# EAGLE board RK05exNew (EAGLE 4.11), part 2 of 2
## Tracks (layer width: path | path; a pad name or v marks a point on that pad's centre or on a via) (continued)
N$3 (continued)
  Top 0.508: E11.13 53.98,139.06 55.24,139.06 E11.12 56.52,140.34 57.78,141.6 80.01,141.6 80.01,137.16 81.28,135.89 81.28,133.35 E10.3
  Bottom 0.508: E10.3 81.92,132.72 83.19,133.99 84.45,133.99 85.72,132.72 E10.5
N$4  (via drill 0.61)
  Top 0.508: v78.74,128.91 78.74,130.81 E10.2 | v85.72,128.91 88.27,131.44 E10.6
  Bottom 0.508: v78.74,128.91 v85.72,128.91
N$5  (via drill 0.61)
  Top 0.508: R10.1 215.9,144.15 215.9,140.97 E2.10 215.9,138.43 213.36,135.89 213.36,133.35 E2.4 213.36,130.81 v213.36,128.91 | v134.62,126.36 134.62,102.87 E5.10
  Bottom 0.508: v134.62,126.36 137.16,128.91 v213.36,128.91
N$6
  Top 0.508: E7.4 78.74,95.25 78.74,100.33 E7.11
N$7
  Top 0.508: E7.5 81.92,93.34 83.19,92.08 85.09,92.08 85.09,99.06 86.36,100.33 E7.8
N$8
  Top 0.508: E11.3 56.52,132.72 62.87,139.06 E11.9
N$9  (via drill 0.61)
  Top 0.508: v83.82,98.42 83.82,100.33 E7.9 | v173.99,99.06 173.99,102.87 176.53,105.41 v176.53,107.31 | v189.23,113.03 190.5,114.3 190.5,127 194.31,130.81 194.31,137.16 195.58,138.43 E4.8
  Bottom 0.508: v83.82,98.42 139.06,98.42 139.7,99.06 v173.99,99.06 | v176.53,107.31 182.25,113.03 v189.23,113.03
N$10
  Top 0.508: R20.1 238.76,38.73 238.76,40.01 C36.1 | E13.3 243.84,11.43 242.57,12.7 242.57,39.37 Q1.E
  Bottom 0.508: R20.1 239.4,38.1 240.66,39.37 241.3,39.37 Q1.E
N$11
  Top 0.508: E8.14 132.08,140.97 132.08,141.6 139.7,149.22 171.45,149.22 171.45,138.43 172.72,137.16 172.72,135.25 C63.2
N$12
  Top 0.508: E8.6 139.7,133.35 143.51,137.16 143.51,140.97 139.7,144.78 137.79,144.78 C62.2
N$13
  Top 0.508: R9.E 161.29,147.32 158.75,144.78 R9.S
  Bottom 0.508: 153.67,142.88 155.57,144.78 156.21,144.78 R9.S | 153.67,142.88 148.59,137.79 131.44,137.79 130.18,139.06 E8.15 | 153.67,142.88 171.45,142.88 172.09,142.24 C63.1
N$14  (via drill 0.61)
  Top 0.508: v143.51,135.25 143.51,134.62 142.24,133.35 E8.7 | v146.05,135.25 146.05,142.88 144.78,144.15 C62.1 144.78,145.41 144.78,146.69 R8.1
  Bottom 0.508: v143.51,135.25 v146.05,135.25
N$15
  Top 0.508: E7.3 76.83,93.34 78.11,92.08 80.01,92.08 80.01,135.89 78.74,137.16 78.74,138.43 E10.13
N$16
  Top 0.508: R21.1 243.84,36.2 243.84,37.47 Q1.B1
N$17
  Top 0.508: Q1.B2 243.84,41.27 243.84,42.55 R22.2
N$18  (via drill 0.61)
  Top 0.508: R22.1 233.68,43.81 233.68,45.09 R23.2 | 187.96,19.05 185.42,21.59 185.42,22.23 C37.2 | 187.96,19.05 E12.13 187.96,19.05 | v191.77,46.99 190.5,45.72 190.5,30.48 187.96,27.94 187.96,19.05
  Bottom 0.508: v191.77,46.99 194.31,49.53 198.75,49.53 202.56,45.72 233.04,45.72 R23.2
N$19  (via drill 0.61)
  Top 0.508: C37.1 193.04,22.23 193.04,21.59 190.5,19.05 E12.12 190.5,16.51 v190.5,14.61 | v89.53,40.01 92.71,36.83 92.71,26.67 100.33,19.05 v100.33,13.34 | v224.79,14.61 224.79,15.24 226.06,16.51 E14.10
  Bottom 0.508: v89.53,40.01 80.01,40.01 76.2,43.81 47.62,43.81 31.11,60.33 E22.1 | 190.5,13.34 210.19,13.34 211.46,12.06 | v100.33,13.34 190.5,13.34 | 211.46,12.06 212.72,10.79 E14.2 | v224.79,14.61 222.25,12.06 211.46,12.06 | 190.5,13.34 v190.5,14.61
N$20  (via drill 0.61)
  Top 0.508: v91.44,8.26 91.44,4.45 94.61,1.27 108.58,1.27 108.58,9.53 E17.6
  Bottom 0.508: v91.44,8.26 94.61,8.26 95.89,9.53 E17.1
N$21  (via drill 0.61)
  Top 0.508: v101.6,50.8 102.87,49.53 102.87,39.37 105.41,36.83 105.41,30.48 102.87,27.94 102.87,15.24 101.6,13.97 101.6,11.43 E17.3
  Bottom 0.508: E17.3 102.23,9.53 103.5,9.53 E17.4 | v101.6,50.8 90.81,50.8 90.17,50.16 84.45,50.16 80.01,54.61 59.69,54.61 57.15,57.15 52.07,57.15 48.9,60.33 E21.1
N$22  (via drill 0.61)
  Top 0.508: E14.15 213.36,19.05 213.36,22.23 C35.1 214,22.86 v216.53,25.4
  Bottom 0.508: v216.53,25.4 220.34,25.4 R25.1
N$23
  Top 0.508: E14.14 216.53,18.41 220.34,22.23 220.34,22.86 C35.2
N$24
  Top 0.508: R28.1 226.06,5.71 226.06,8.89 E14.7 226.06,11.43 227.33,12.7 227.33,19.68 230.5,22.86 C25.1
N$25
  Top 0.508: E14.6 223.52,11.43 222.25,12.7 222.25,20.95 223.52,22.23 C25.2
N$26  (via drill 0.61)
  Top 0.508: v25.4,13.34 25.4,12.7 23.5,10.79 E20.4 | v49.53,14.61 50.8,15.88 50.8,16.51 E19.13
  Bottom 0.508: v25.4,13.34 26.67,14.61 v49.53,14.61
N$27
  Top 0.508: E20.5 25.4,8.89 25.4,6.35 30.48,1.27 52.07,1.27 52.07,15.24 53.34,16.51 E19.12
N$28
  Top 0.508: E19.5 53.98,9.53 56.52,6.99 83.82,6.99 83.82,8.89 E16.6
N$29
  Top 0.508: E3.15 167.64,64.77 168.91,66.04 168.91,71.75 170.18,73.03 170.18,128.27 167.64,130.81 E6.6
N$30
  Bottom 0.508: RUN.2 29.21,84.45 33.02,88.27 41.91,88.27 RTZ.1
N$31  (via drill 0.61)
  Top 0.508: v160.02,144.15 160.02,140.97 E6.12 | v180.97,144.15 184.15,140.97 v184.15,72.39 | v173.99,70.48 170.18,66.67 170.18,64.77 E3.14
  Bottom 0.508: v180.97,144.15 v160.02,144.15 | v184.15,72.39 182.25,70.48 v173.99,70.48
N$32  (via drill 0.61)
  Top 0.508: v160.66,135.25 158.75,133.35 158.75,99.69 160.02,98.42 160.02,72.39 v165.1,67.31
  Bottom 0.508: v160.66,135.25 164.47,139.06 E6.10 | v165.1,67.31 167,65.41 170.81,65.41 172.09,64.14 E3.13
N$33
  Top 0.508: E6.8 170.18,138.43 171.45,137.16 171.45,122.56 173.99,120.02 173.99,104.14 172.72,102.87 172.72,73.66 177.16,69.22 177.16,66.67 175.26,64.77 E3.12
N$34
  Bottom 0.508: E6.2 158.12,131.44 159.38,131.44 E6.3
N$35
  Bottom 0.508: E19.4 51.44,10.79 55.24,14.61 83.19,14.61 85.72,17.14 E16.8
N$36  (via drill 0.61)
  Top 0.508: E5.2 127.64,93.34 128.91,93.34 E5.3 | v154.94,97.79 154.94,125.09 153.67,126.36 153.67,136.53 159.38,136.53 161.29,138.43 161.29,141.6 163.19,141.6 163.83,140.97 163.83,134.62 162.56,133.35 E6.4
  Bottom 0.508: v154.94,97.79 153.67,96.52 139.7,96.52 139.06,95.89 131.44,95.89 130.18,94.61 E5.3
N$37
  Top 0.508: R1.1 71.12,79.38 71.12,83.19 ADDR_INV.A
N$38
  Top 0.508: R2.1 81.28,79.38 81.28,83.19 SEEK_INC.A
N$39
  Top 0.508: R3.1 99.06,79.38 99.06,83.19 POWER_ON.A
N$40
  Bottom 0.508: 53.98,19.68 29.84,19.68 28.57,18.41 E20.11 | 53.98,19.68 55.24,18.41 E19.11 | 53.98,19.68 109.86,19.68 111.12,18.41 E17.8
N$41
  Bottom 0.508: 46.35,15.88 22.23,15.88 20.95,17.14 E20.14 | 46.35,15.88 47.62,17.14 E19.14 | 46.35,15.88 74.3,15.88 75.56,17.14 E16.12
N$42
  Top 0.508: C38.1 208.28,20.95 208.28,24.77 210.82,27.3 R29.1 210.82,28.57 210.82,29.21 215.9,34.29 E25.2
N$43  (via drill 0.61)
  Top 0.508: R29.2 221.62,27.94 222.88,27.94 R30.2 | v219.07,32.38 219.71,33.02 219.71,40.64 218.44,41.91 E25.6
  Bottom 0.508: R32.1 235.59,25.4 234.31,26.67 225.43,26.67 224.16,27.94 R30.2 | v219.07,32.38 219.07,28.57 220.98,28.57 R29.2
N$44
  Top 0.508: R31.2 233.68,26.04 233.68,27.3 R30.1
  Bottom 0.508: E25.3 219.07,34.92 226.06,27.94 233.04,27.94 R30.1
N$45  (via drill 0.61)
  Top 0.508: v95.25,95.89 95.25,104.14 93.98,105.41 93.98,115.57 94.61,116.2 94.61,135.25 91.44,138.43 E10.8 | v91.44,54.61 v91.44,95.25 | v115.57,53.98 122.56,60.96 v122.56,71.12 | v147.96,80.64 149.22,81.92 154.94,81.92 v154.94,83.82 | v173.99,86.36 177.8,90.17 177.8,92.71 E34.1
  Bottom 0.508: E34.1 178.44,93.34 179.71,93.34 E34.2 | v95.25,95.89 94.61,95.25 v91.44,95.25 | v91.44,54.61 92.08,53.98 v115.57,53.98 | v122.56,71.12 133.99,71.12 143.51,80.64 v147.96,80.64 | v154.94,83.82 157.48,86.36 v173.99,86.36
N$46  (via drill 0.61)
  Top 0.508: v30.48,22.86 30.48,31.75 27.94,34.29 E23.2 | v158.75,22.23 161.29,19.68 161.29,12.7 162.56,11.43 E15.2 162.56,8.89 162.56,8.26 v163.83,6.99 | v186.06,6.99 187.96,8.89 E12.2
  Bottom 0.508: v30.48,22.86 71.75,22.86 73.03,24.13 118.75,24.13 120.65,22.23 v158.75,22.23 | v163.83,6.99 v186.06,6.99
N$47  (via drill 0.61)
  Top 0.508: v166.37,2.54 160.02,8.89 E15.1 | v215.9,2.54 218.44,5.08 218.44,8.89 E14.4
  Bottom 0.508: v166.37,2.54 v215.9,2.54
N$48
  Top 0.508: D3.A 60.96,59.69 63.5,62.23 63.5,67.31 D2.C
N$49  (via drill 0.61)
  Top 0.508: E34.6 182.25,100.97 180.97,100.97 E34.7 180.34,102.87 v180.34,118.75 | v128.27,137.79 130.81,137.79 130.81,144.15 133.35,146.69 133.35,147.96 136.53,151.13 173.99,151.13 v173.99,139.7 | v176.53,137.79 v176.53,122.56
  Bottom 0.508: v128.27,137.79 85.72,137.79 84.45,139.06 E10.11 | v173.99,139.7 175.9,137.79 v176.53,137.79 | v176.53,122.56 v180.34,118.75
N$53
  Top 0.508: D4.A 58.42,59.69 60.96,62.23 60.96,67.31 D3.C
N$55  (via drill 0.61)
  Top 0.508: v198.12,3.81 193.04,8.89 E12.4
  Bottom 0.508: v198.12,3.81 237.49,3.81 242.57,8.89 242.57,17.14 243.21,17.14 E13.6
N$57  (via drill 0.61)
  Top 0.508: v26.67,6.99 26.67,33.02 25.4,34.29 E23.1 | v117.47,3.81 127,13.34 133.35,13.34 133.35,19.05 134.62,20.32 134.62,24.13 135.25,24.77 138.43,24.77 v138.43,23.5 138.43,12.7 139.7,11.43 E18.3
  Bottom 0.508: E13.7 240.66,17.14 239.4,15.88 222.88,15.88 221.62,17.14 E14.12 220.34,17.14 219.07,15.88 205.1,15.88 199.39,21.59 179.07,21.59 178.44,22.23 160.66,22.23 159.38,23.5 v138.43,23.5 | v26.67,6.99 29.84,3.81 v117.47,3.81
N$58  (via drill 0.61)
  Top 0.508: v195.58,22.86 194.31,21.59 194.31,16.51 193.04,15.24 193.04,12.06 187.32,12.06 186.06,10.79 E12.1 | E13.5 246.38,19.05 246.38,22.23 D5.C 246.38,23.5 246.38,24.77 R32.2
  Bottom 0.508: v195.58,22.86 211.46,22.86 212.72,24.13 231.78,24.13 234.31,21.59 243.84,21.59 245.11,22.86 D5.C
N$59
  Top 0.508: E16.3 76.2,11.43 78.74,13.97 78.74,16.51 E16.11
  Bottom 0.508: E15.3 164.47,10.79 163.19,12.06 78.11,12.06 76.83,10.79 E16.3
N$60
  Bottom 0.508: E23.13 28.57,42.55 31.11,40.01 37.47,40.01 40.01,42.55 E23.8
N$61  (via drill 0.61)
  Top 0.508: v163.83,14.61 163.83,8.26 175.9,8.26 176.53,8.89 176.53,22.23 180.34,22.23 184.15,18.41 184.15,13.34 191.13,13.34 191.77,13.97 191.77,15.24 193.04,16.51 E12.11 | v121.28,23.5 v130.18,14.61
  Bottom 0.508: E23.9 37.47,42.55 36.2,41.27 32.38,41.27 31.11,42.55 E23.12 29.84,43.81 28.57,45.09 21.59,45.09 21.59,33.66 31.11,24.13 67.31,24.13 68.58,25.4 119.38,25.4 v121.28,23.5 | v130.18,14.61 v163.83,14.61
N$62
  Top 0.508: E16.2 74.3,9.53 75.56,8.26 82.55,8.26 82.55,11.43 83.19,12.06 92.71,12.06 92.71,6.99 95.89,3.81 102.87,3.81 102.87,13.97 104.14,15.24 104.14,16.51 E17.11
N$63
  Bottom 0.508: 104.78,15.88 103.5,15.88 102.23,17.14 E17.12 | 104.78,15.88 106.05,17.14 E17.10 | 104.78,15.88 112.39,15.88 116.2,19.68 193.68,19.68 194.94,18.41 E12.10
N$64  (via drill 0.61)
  Top 0.508: v121.92,85.09 121.92,83.82 111.12,83.82 109.86,85.09 109.86,92.08 109.22,92.71 E26.6 | v137.79,85.09 140.97,81.92 v140.97,76.2 | v163.19,72.39 166.37,69.22 166.37,48.9 170.18,45.09 170.18,44.45 E30.7
  Bottom 0.508: v121.92,85.09 v137.79,85.09 | v140.97,76.2 144.78,72.39 v163.19,72.39
N$65  (via drill 0.61)
  Top 0.508: v122.56,86.36 115.57,93.34 115.57,96.52 111.76,100.33 E26.8 | v131.44,86.36 133.99,83.82 133.99,55.24 134.62,54.61 v134.62,50.8
  Bottom 0.508: v131.44,86.36 v122.56,86.36 | v134.62,50.8 136.53,48.9 167,48.9 172.09,43.81 E30.6
N$66  (via drill 0.61)
  Top 0.508: v96.52,46.99 96.52,53.98 97.79,55.24 97.79,75.56 101.6,79.38 101.6,92.71 E26.3
  Bottom 0.508: v96.52,46.99 105.41,46.99 105.41,41.91 106.05,41.27 112.39,41.27 113.67,42.55 118.11,42.55 120.65,40.01 133.99,40.01 135.25,38.73 167,38.73 169.54,36.2 E30.2
N$67  (via drill 0.61)
  Top 0.508: v144.78,37.47 142.88,39.37 142.88,53.98 143.51,54.61 143.51,57.15 142.88,57.78 140.97,57.78 140.97,54.61 140.34,53.98 135.89,53.98 v135.89,64.77 | v118.75,66.04 118.75,77.47 117.47,78.74 109.86,78.74 v109.86,79.38 | v104.78,82.55 102.87,84.45 102.87,99.06 104.14,100.33 E26.11
  Bottom 0.508: v144.78,37.47 165.74,37.47 167,36.2 E30.1 | v135.89,64.77 134.62,66.04 v118.75,66.04 | v109.86,79.38 106.68,82.55 v104.78,82.55
N$68
  Top 0.508: E31.6 152.4,44.45 153.67,45.72 153.67,60.96 154.94,62.23 E27.8
N$69
  Top 0.508: E31.7 149.86,44.45 149.86,50.8 152.4,53.34 152.4,54.61 E27.6
N$70
  Top 0.508: E31.1 147.32,36.83 148.59,38.1 148.59,60.96 147.32,62.23 E27.11
N$71  (via drill 0.61)
  Top 0.508: v151.13,50.16 151.13,38.1 149.86,36.83 E31.2 | v144.78,50.8 144.78,54.61 E27.3
  Bottom 0.508: v151.13,50.16 150.5,50.8 v144.78,50.8
N$72  (via drill 0.61)
  Top 0.508: v114.3,45.72 111.76,48.26 111.76,54.61 E28.6
  Bottom 0.508: v114.3,45.72 109.22,45.72 107.31,43.81 E32.7
N$73
  Top 0.508: E32.2 106.68,36.83 105.41,38.1 105.41,53.34 104.14,54.61 E28.3
N$75  (via drill 0.61)
  Top 0.508: v97.79,52.07 97.79,40.64 93.98,36.83 E29.6
  Bottom 0.508: v97.79,52.07 97.16,52.7 89.53,52.7 87.63,54.61 87.63,59.69 84.45,62.87 E33.7
N$76
  Top 0.508: E29.3 86.36,36.83 85.09,38.1 85.09,53.34 83.82,54.61 E33.2
N$77  (via drill 0.61)
  Top 0.508: v87.63,51.44 87.63,45.72 88.9,44.45 E29.11
  Bottom 0.508: v87.63,51.44 85.09,53.98 83.19,53.98 81.92,55.24 E33.1
N$78  (via drill 0.61)
  Top 0.508: v95.25,57.15 95.25,45.72 96.52,44.45 E29.8
  Bottom 0.508: v95.25,57.15 93.98,58.42 90.17,58.42 86.36,62.23 E33.6
N$80
  Top 0.508: E32.1 104.14,36.83 100.33,40.64 100.33,52.07 102.87,54.61 102.87,58.42 106.68,62.23 E28.11
N$81
  Top 0.508: E32.6 109.22,44.45 107.95,45.72 107.95,57.15 113.67,62.87 E28.8
N$82
  Top 0.508: E18.10 144.15,17.14 142.88,17.14 E18.11
  Bottom 0.508: E18.13 137.79,17.14 139.06,17.14 E18.12 140.34,17.14 141.6,17.14 E18.11 | E12.8 200.03,17.14 198.75,15.88 146.69,15.88 145.41,17.14 E18.10
NEG1_DETECT_L
  Top 0.508: E23.6 38.1,36.83 35.56,39.37 35.56,41.91 E23.10
OSC_L
  Top 0.508: E16.13 73.66,19.05 73.66,22.23 R35.1 73.66,23.5 67.94,29.21 67.94,46.99 66.67,48.26 FUNCTION.3
RANDOM_L  (via drill 0.61)
  Top 0.508: 133.35,50.8 133.35,50.16 140.34,43.18 140.34,19.68 140.97,19.05 v140.97,6.99 | 133.35,50.8 133.35,54.61 132.72,55.24 D1.C | E12.3 190.5,8.89 190.5,5.71 R34.1 | v88.9,46.99 v91.44,49.53 | v132.72,50.8 133.35,50.8
  Bottom 0.508: v140.97,6.99 144.15,3.81 188.59,3.81 189.87,5.08 R34.1 | v88.9,46.99 72.39,46.99 71.75,46.35 FUNCTION.4 | v91.44,49.53 121.92,49.53 123.19,50.8 v132.72,50.8
READ_CLOCK
  Top 0.508: RN1.3 200.66,95.25 200.66,92.71 RN5.3 200.66,90.17 200.66,84.45 J1.F
READ_DATA
  Top 0.508: RN1.2 198.12,95.25 198.12,92.71 RN5.2 198.12,90.17 198.12,84.45 J1.D
REV_L  (via drill 0.61)
  Top 0.508: 89.53,23.5 85.09,19.05 85.09,15.24 81.28,11.43 E16.5 | 89.53,23.5 94.61,23.5 99.06,19.05 E17.13 | v76.2,31.11 76.2,43.81 69.85,50.16 69.85,74.3 66.67,77.47 66.67,85.09 66.04,85.72 R33.1 | 89.53,23.5 v89.53,30.48
  Bottom 0.508: R33.1 65.41,86.36 63.5,88.27 59.69,88.27 FWD/REV.1 | v76.2,31.11 76.83,30.48 v89.53,30.48
RK05_AU2
  Top 0.508: RN3.2 195.58,57.15 195.58,59.69 RN7.2 195.58,62.23 195.58,67.94 J2.A
RK05_BH2
  Top 0.508: RN2.4 236.22,95.25 236.22,92.71 RN6.4 236.22,90.17 236.22,84.45 J1.NN
RTZ_L  (via drill 0.61)
  Top 0.508: v97.16,13.34 99.06,11.43 E17.2 | E22.7 33.02,69.85 34.29,71.12 v34.29,78.74 34.29,84.45 35.56,85.72 R24.1 | v64.14,48.26 64.14,18.41 71.12,11.43 E16.1
  Bottom 0.508: v97.16,13.34 74.3,13.34 71.75,10.79 E16.1 | v34.29,78.74 41.91,78.74 RTZ.3 | v64.14,48.26 60.33,52.07 46.99,52.07 40.01,59.05 37.47,59.05 36.83,59.69 36.83,66.04 35.56,66.04 33.66,67.94 E22.7
RUN_L  (via drill 0.61)
  Top 0.508: v196.85,6.99 195.58,8.26 194.94,8.26 194.31,8.89 194.31,13.97 196.85,16.51 196.85,23.5 196.22,24.13 189.23,24.13 189.23,16.51 188.59,15.88 186.69,15.88 186.69,19.05 v179.71,26.04 | v108.58,30.48 v111.12,27.94 | v27.3,66.04 21.59,71.75 21.59,84.45 20.32,85.72 R19.1
  Bottom 0.508: R19.1 20.95,86.36 22.86,88.27 26.67,88.27 RUN.1 | v196.85,6.99 238.12,6.99 240.66,9.53 E13.2 | v179.71,26.04 158.12,26.04 154.31,29.84 137.16,29.84 135.89,28.57 131.44,28.57 130.81,29.21 121.28,29.21 120.02,27.94 v111.12,27.94 | v108.58,30.48 106.68,32.38 85.72,32.38 84.45,33.66 83.19,33.66 82.55,34.29 82.55,37.47 51.44,37.47 29.21,59.69 29.21,66.04 v27.3,66.04
SECTOR_0L  (via drill 0.61)
  Top 0.508: v178.44,46.35 179.07,45.72 179.07,41.91 184.15,36.83 184.15,29.21 SECTOR.1
  Bottom 0.508: v178.44,46.35 174.62,46.35 165.74,55.24 E3.1
SECTOR_1L  (via drill 0.61)
  Top 0.508: v170.18,48.9 170.18,52.07 167.64,54.61 E3.2 | v177.8,45.09 177.8,35.56 180.34,33.02 SECTOR.2
  Bottom 0.508: v170.18,48.9 173.99,45.09 v177.8,45.09
SECTOR_2L  (via drill 0.61)
  Top 0.508: v171.45,41.27 171.45,53.34 170.18,54.61 E3.3
  Bottom 0.508: v171.45,41.27 173.99,38.73 179.07,38.73 SECTOR.3
SECTOR_3L  (via drill 0.61)
  Top 0.508: v180.97,49.53 180.97,44.45 SECTOR.4
  Bottom 0.508: v180.97,49.53 172.72,49.53 172.72,54.61 E3.4
SECTOR_4L  (via drill 0.61)
  Top 0.508: v175.26,52.07 175.26,54.61 E3.5 | v180.97,52.07 184.78,48.26 SECTOR.5
  Bottom 0.508: v175.26,52.07 v180.97,52.07
SECTOR_5L
  Bottom 0.508: E3.6 177.16,55.24 175.26,53.34 174.62,53.34 173.99,52.7 173.99,50.8 188.59,50.8 189.87,49.53 SECTOR.6
SECTOR_6L  (via drill 0.61)
  Top 0.508: v179.71,48.26 179.71,53.98 180.34,54.61 E3.7
  Bottom 0.508: v179.71,48.26 182.25,45.72 194.31,45.72 195.58,46.99 SECTOR.7
SECTOR_7L  (via drill 0.61)
  Top 0.508: v187.32,63.5 189.23,61.59 v189.23,52.07 | v198.12,50.8 199.39,49.53 199.39,43.81 SECTOR.8
  Bottom 0.508: v187.32,63.5 183.51,63.5 E3.9 | v189.23,52.07 190.5,50.8 v198.12,50.8
SECTOR_8L  (via drill 0.61)
  Top 0.508: v181.61,53.98 181.61,57.15 180.34,58.42 180.34,62.23 E3.10 | v201.93,52.07 201.93,38.73 SECTOR.9
  Bottom 0.508: v181.61,53.98 182.25,53.34 194.31,53.34 195.58,52.07 v201.93,52.07
SECTOR_9L  (via drill 0.61)
  Top 0.508: v196.85,66.67 196.85,49.53 198.12,48.26 198.12,34.29 199.39,33.02 SECTOR.10
  Bottom 0.508: v196.85,66.67 189.87,66.67 188.59,65.41 179.71,65.41 178.44,64.14 E3.11
SECTOR_SELECT_L  (via drill 0.61)
  Top 0.508: v73.66,76.2 73.66,90.17 71.12,92.71 E7.1 | v101.6,73.03 104.78,69.85 v104.78,66.04 | v130.18,67.31 132.72,69.85 v132.72,72.39 | v157.48,74.93 158.75,73.66 158.75,69.22 163.83,64.14 163.83,49.53 168.91,44.45 168.91,41.91 171.45,39.37 176.53,39.37 176.53,59.69 179.07,62.23 179.07,64.77 179.71,65.41 181.61,65.41 181.61,59.69 186.69,54.61 186.69,36.83 SECTOR.A
  Bottom 0.508: v73.66,76.2 76.83,73.03 v101.6,73.03 | v104.78,66.04 116.84,66.04 118.11,67.31 v130.18,67.31 | v132.72,72.39 142.24,81.92 150.5,81.92 v157.48,74.93
SEEK_INCOMPLETE_L  (via drill 0.61)
  Top 0.508: v71.75,64.77 79.38,72.39 79.38,84.45 80.64,85.72 SEEK_INC.B
  Bottom 0.508: v71.75,64.77 57.15,64.77 53.98,61.59 E21.3
SELECT_0L  (via drill 0.61)
  Top 0.508: J2.AA 223.52,67.94 223.52,62.23 RN8.10 223.52,59.69 223.52,57.15 RN4.10 223.52,54.61 223.52,34.92 219.71,31.11 219.71,26.67 214.63,21.59 214.63,16.51 212.09,13.97 212.09,1.27 182.25,1.27 179.07,4.45 179.07,19.68 v177.8,20.95 | v117.47,22.86 117.47,31.75 118.11,32.38 118.11,44.45 118.75,45.09 DRIVE.1
  Bottom 0.508: v117.47,22.86 119.38,20.95 v177.8,20.95
SELECT_1L  (via drill 0.61)
  Top 0.508: R69.1 218.44,53.98 218.44,57.78 R70.2 218.44,59.05 218.44,67.94 J2.W | v123.83,33.66 123.83,48.26 DRIVE.2 | v199.39,26.67 201.93,24.13 v201.93,15.88 | v217.81,14.61 219.71,16.51 219.71,19.68 222.25,22.23 222.25,26.04 222.88,26.67 224.79,26.67 v224.79,53.34
  Bottom 0.508: v123.83,33.66 125.09,32.38 160.66,32.38 165.74,27.3 183.51,27.3 184.15,26.67 186.69,26.67 189.23,29.21 192.41,29.21 194.94,26.67 v199.39,26.67 | v201.93,15.88 203.2,14.61 v217.81,14.61 | v224.79,53.34 224.16,53.98 222.25,53.98 218.44,57.78 R70.2
SELECT_2L  (via drill 0.61)
  Top 0.508: J2.S 213.36,67.94 213.36,62.23 RN7.9 213.36,59.69 213.36,57.15 RN3.9 213.36,54.61 212.09,53.34 212.09,31.75 v209.55,29.21 | v160.02,47.62 161.29,46.35 161.29,29.21 163.83,26.67 v163.83,23.5 | v203.2,24.13 204.47,25.4 v204.47,29.21
  Bottom 0.508: v160.02,47.62 132.08,47.62 130.81,48.9 DRIVE.3 | v163.83,23.5 184.15,23.5 184.78,24.13 v203.2,24.13 | v209.55,29.21 v204.47,29.21
SELECT_3L  (via drill 0.61)
  Top 0.508: J2.M 208.28,67.94 208.28,62.23 RN7.7 207.65,60.33 207.01,59.69 207.01,57.15 207.65,56.52 RN3.7 208.91,55.24 209.55,54.61 209.55,31.75 v208.28,30.48 | v159.38,46.35 160.02,45.72 v160.02,34.29
  Bottom 0.508: v159.38,46.35 135.25,46.35 DRIVE.4 | v160.02,34.29 163.83,30.48 v208.28,30.48
STEP_L  (via drill 0.61)
  Top 0.508: R37.1 134.62,5.71 134.62,8.89 E18.1 134.62,11.43 135.89,12.7 v135.89,23.5 | v113.67,48.26 113.67,48.9 120.65,55.88 D1.A 121.92,55.24 121.92,26.67 v124.46,24.13
  Bottom 0.508: v113.67,48.26 70.48,48.26 68.58,46.35 56.52,46.35 FUNCTION.1 | v135.89,23.5 135.25,24.13 v124.46,24.13
VCC  (via drill 0.61)
  Top 0.508: C16.1 69.22,17.78 70.48,17.78 E16.14 71.12,19.05 72.39,20.32 v72.39,20.95 | v90.17,22.23 93.98,18.41 C17.1 94.61,17.78 95.89,17.78 E17.14 96.52,16.51 95.25,15.24 95.25,6.99 96.52,5.71 R26.2 | C19.1 41.27,17.78 42.55,17.78 E19.16 43.18,19.05 45.09,20.95 45.09,59.69 44.45,60.33 44.45,66.67 45.72,67.94 C21.1 | R36.2 50.8,75.56 49.53,74.3 49.53,71.12 48.26,69.85 E21.8 | C20.1 13.34,17.78 14.61,17.78 E20.16 15.24,19.05 21.59,25.4 21.59,41.27 22.86,42.55 C23.1 23.5,43.18 24.77,43.18 E23.14 25.4,44.45 25.4,50.8 27.3,52.7 C68.+ 28.57,53.98 29.21,54.61 29.21,64.77 30.48,66.04 30.48,67.31 E22.8 | v35.56,71.12 35.56,75.56 R24.2 | 10.79,95.89 19.05,87.63 19.05,78.11 20.32,76.83 R19.2 | 10.79,95.89 8.26,98.42 C60.+ | E13.8 238.12,17.78 236.85,17.78 C13.1 | R25.2 210.82,24.77 210.82,19.05 E14.16 210.19,17.78 208.91,17.78 C14.1 208.28,18.41 207.01,19.68 207.01,37.47 208.28,38.73 208.28,52.7 R69.2 | C41.1 248.28,55.88 247.01,55.88 RN4.1 | R11.2 220.34,99.06 v217.81,101.6 217.17,102.23 217.17,117.47 218.44,118.75 R7.2 | R46.2 233.68,99.69 234.95,100.97 234.95,117.47 233.68,118.75 R5.2 | E2.14 205.1,139.7 203.84,139.7 C2.1 | E1.14 230.5,139.7 229.24,139.7 C1.1 228.6,140.34 228.6,141.6 226.06,144.15 R10.2 | RN1.1 194.94,96.52 193.68,96.52 C42.1 193.04,95.89 189.23,92.08 189.23,85.09 188.59,84.45 C52.+ 188.59,83.19 191.13,80.64 191.13,71.12 194.31,67.94 194.31,58.42 193.04,57.15 RN3.1 | C4.1 178.44,139.7 179.71,139.7 E4.14 180.34,138.43 179.07,137.16 179.07,120.65 | v157.48,101.6 157.48,89.53 R6.2 | C9.1 175.9,101.6 177.16,101.6 E34.8 177.8,102.87 177.8,113.03 v176.53,114.3 176.53,120.65 179.07,120.65
  Top 0.508: 179.07,120.65 180.97,120.65 182.25,119.38 R13.2 | C12.1 182.25,17.78 180.34,15.88 180.34,5.71 R34.2 | C31.1 145.41,43.18 146.69,43.18 E31.8 147.32,41.91 146.05,40.64 146.05,29.21 145.41,28.57 C67.+ | E30.8 167,43.18 165.74,43.18 C30.1 165.1,43.81 163.83,45.09 163.83,47.62 158.12,53.34 | 158.75,17.78 158.12,17.78 C15.1 157.48,18.41 157.48,45.72 158.12,46.35 158.12,53.34 | 158.75,17.78 159.38,17.78 E15.14 | 158.12,53.34 158.12,58.42 162.56,62.87 C3.1 | C61.+ 139.06,86.36 136.53,86.36 136.53,66.04 137.16,65.41 137.16,64.14 C27.1 | 158.75,17.78 v158.75,6.99 | E5.14 124.46,100.33 124.46,95.25 E5.1 123.83,93.34 123.83,82.55 117.47,82.55 POWER.2 | C5.1 122.56,101.6 123.83,101.6 E5.14 | E6.14 154.31,139.7 153.03,139.7 C6.1 152.4,140.34 152.4,144.78 150.5,146.69 R9.A | R18.2 122.56,139.7 123.83,139.7 C8.1 125.09,139.7 126.36,139.7 E8.16 127,138.43 127,137.16 128.27,135.89 | 128.27,135.89 130.81,133.35 130.81,96.52 132.08,95.25 E5.4 132.08,92.71 132.08,88.9 v133.99,87 | 128.27,135.89 128.27,128.91 127,127.64 R17.2 127,126.36 127,120.02 R45.1 127,118.75 127,116.2 124.46,113.67 124.46,102.87 E5.14 | 64.77,58.42 65.41,58.42 R27.2 | 64.77,58.42 64.14,58.42 D2.A | 64.77,58.42 64.77,74.3 66.04,75.56 R33.2 | E29.14 80.64,43.18 79.38,43.18 C29.1 78.74,43.81 78.74,55.24 C33.1 78.74,56.52 78.74,59.69 81.28,62.23 E33.8 | C11.1 48.9,139.7 50.16,139.7 E11.14 50.8,138.43 49.53,137.16 49.53,121.28 50.8,120.02 R40.1 | E24.14 100.97,139.7 99.69,139.7 C24.1 99.06,139.06 96.52,136.53 96.52,120.02 R43.1 96.52,118.75 96.52,116.84 95.25,115.57 95.25,108.58 96.52,107.31 96.52,102.87 E26.14 96.52,100.33 96.52,99.69 97.79,98.42 97.79,92.71 96.52,91.44 96.52,64.14 C28.1
  Top 0.508: E10.14 75.56,139.7 74.3,139.7 C10.1 73.66,139.06 67.31,132.72 67.31,117.47 | E7.14 70.48,101.6 69.22,101.6 C7.1 68.58,102.23 68.58,116.2 67.31,117.47 | 67.31,117.47 66.04,118.75 R41.1 | 10.79,95.89 19.05,104.14 19.05,117.47 20.32,118.75 R38.1
  Bottom 0.508: v90.17,22.23 85.09,22.23 84.45,22.86 R35.2 83.19,22.86 81.92,21.59 73.03,21.59 v72.39,20.95 18.41,20.95 15.88,18.41 E20.16 | E18.14 133.99,17.78 132.72,17.78 C18.1 131.44,17.78 128.27,14.61 99.69,14.61 97.16,17.14 E17.14 | E21.8 47.62,68.58 46.35,68.58 C21.1 45.09,68.58 43.18,70.48 34.92,70.48 | R19.2 20.32,75.56 20.32,69.22 27.94,69.22 C22.1 28.57,68.58 29.84,68.58 E22.8 31.11,69.22 32.38,70.48 34.92,70.48 | 34.92,70.48 v35.56,71.12 | C13.1 235.59,17.78 233.68,19.68 212.72,19.68 211.46,18.41 E14.16 | C40.1 191.13,55.88 192.41,55.88 RN3.1 193.68,55.24 194.94,53.98 207.01,53.98 207.65,53.34 R69.2 208.91,53.34 210.19,52.07 229.24,52.07 230.5,53.34 R147.2 231.78,53.34 232.41,53.98 244.47,53.98 245.75,55.24 RN4.1 | R46.2 234.31,99.06 234.95,98.42 239.4,98.42 240.66,97.16 RN2.2 241.94,95.89 243.21,95.89 RN2.1 244.47,97.16 245.11,97.16 246.38,98.42 C43.1 | v217.81,101.6 214,101.6 R16.2 | R50.2 225.43,101.6 222.88,99.06 221.62,99.06 R11.2 220.34,99.06 219.71,98.42 190.5,98.42 | R7.2 219.07,119.38 221.62,116.84 230.5,116.84 233.04,119.38 R5.2 | E2.14 206.38,140.34 207.65,141.6 222.25,141.6 225.43,144.78 R10.2 | v157.48,101.6 174.62,101.6 C9.1 | v176.53,114.3 173.35,114.3 R12.2 | 190.5,98.42 189.23,99.69 179.71,99.69 178.44,100.97 E34.8 | 190.5,98.42 192.41,96.52 C42.1 | C2.1 202.56,139.7 200.66,141.6 182.25,141.6 180.97,140.34 E4.14 | E12.14 184.78,17.78 183.51,17.78 C12.1 | 158.75,5.08 179.71,5.08 R34.2 180.97,5.08 186.06,5.08 187.32,6.35 191.13,6.35 191.77,5.71 214.63,5.71 215.26,5.08 R28.2 | 158.75,5.08 145.41,5.08 R37.2 | C27.1 137.79,63.5 139.06,63.5 E27.14 140.34,64.14 141.6,65.41 160.02,65.41 161.93,63.5 C3.1 163.19,63.5 164.47,63.5 E3.16
  Bottom 0.508: E31.8 147.96,43.81 149.22,45.09 162.56,45.09 164.47,43.18 C30.1 | v158.75,6.99 158.75,5.08 | R4.2 142.88,109.22 145.41,109.22 146.05,108.58 146.05,106.68 127,106.68 124.46,104.14 124.46,102.87 E5.14 | 133.99,146.05 129.54,141.6 128.91,141.6 127.64,140.34 E8.16 | 133.99,146.05 134.62,146.69 R8.2 | 133.99,146.05 147.32,146.05 148.59,147.32 R9.A | E32.8 103.5,43.18 102.23,43.18 C32.1 100.97,43.18 99.06,45.09 83.19,45.09 81.92,43.81 E29.14 | E28.14 98.42,63.5 97.16,63.5 C28.1 95.89,63.5 94.61,64.77 90.17,64.77 89.53,65.41 83.19,65.41 81.92,64.14 E33.8 | R27.2 66.67,58.42 69.22,55.88 78.11,55.88 C33.1 | 32.38,116.84 23.5,116.84 20.95,119.38 R38.1 | 32.38,116.84 34.92,119.38 R39.1 | 32.38,116.84 47.62,116.84 50.16,119.38 R40.1 51.44,119.38 53.98,116.84 69.22,116.84 | E26.14 95.89,101.6 94.61,101.6 C26.1 | 78.11,116.84 80.64,119.38 R42.1 | 78.11,116.84 69.22,116.84 | 69.22,116.84 66.67,119.38 R41.1 | 93.34,116.84 95.89,119.38 R43.1 | 93.34,116.84 78.11,116.84 | 108.58,116.84 111.12,119.38 R44.1 | 108.58,116.84 93.34,116.84 | 108.58,116.84 123.83,116.84 126.36,119.38 R45.1 | v133.99,87 139.06,87 C61.+ | C4.1 177.16,139.7 175.9,140.97 171.45,140.97 170.81,141.6 156.84,141.6 155.57,140.34 E6.14
WRITE_GATE
  Top 0.508: E2.1 205.74,133.35 208.28,135.89 208.28,138.43 E2.13 | E5.13 127,102.87 129.54,105.41 129.54,130.81 E8.2 | E8.11 139.06,140.34 137.79,141.6 133.35,141.6 133.35,134.62 132.08,133.35 E8.3
  Bottom 0.508: 76.2,137.79 79.38,137.79 80.64,139.06 E10.12 | 76.2,137.79 66.67,137.79 61.59,132.72 E11.5 | E2.1 205.1,132.72 203.84,133.99 173.99,133.99 173.35,133.35 171.45,133.35 170.81,133.99 133.99,133.99 132.72,132.72 E8.3 131.44,131.44 130.18,131.44 E8.2 128.91,132.72 126.36,135.25 76.2,135.25 76.2,137.79
WRITE_H  (via drill 0.61)
  Top 0.508: v82.55,144.15 82.55,134.62 83.82,133.35 E10.4 | v226.69,149.22 234.95,140.97 234.95,122.56 232.41,120.02 232.41,111.12 233.68,109.86 R5.1
  Bottom 0.508: v82.55,144.15 123.19,144.15 125.09,142.24 128.27,142.24 128.91,142.88 129.54,142.88 133.35,146.69 133.35,149.22 v226.69,149.22 238.12,149.22 245.11,142.24 247.65,142.24 247.65,90.81 245.11,88.27 166.37,88.27 WRITE.1
WRITE_L  (via drill 0.61)
  Top 0.508: v77.47,136.53 77.47,134.62 76.2,133.35 E10.1 | v154.94,135.25 156.21,133.99 156.21,80.64 157.48,79.38 R6.1
  Bottom 0.508: v77.47,136.53 153.67,136.53 v154.94,135.25 | WRITE.3 163.83,78.74 158.12,78.74 R6.1

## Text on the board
Top: RK05 Exerciser | VRS
Bottom: VRS | RK05 Exerciser
tPlace: Note: SIP resistors must be 200mW parts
